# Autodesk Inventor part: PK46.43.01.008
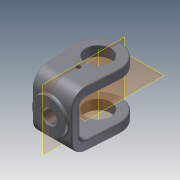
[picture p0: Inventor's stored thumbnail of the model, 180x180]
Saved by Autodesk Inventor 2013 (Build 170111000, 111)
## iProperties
Shininess: 64.0
Length Units: 11269
Angle Units: 11279
Time Units: 11290
Mass Units: 11283
Length Display Precision: 3
Angle Display Precision: 2
Compacted: True
Part Number: PK46.43.01.008
Document SubType Name: Modeling
Created: 2004-11
Material: Steel, High Strength Low Alloy
Designer: ELarisa
Manufacturer: Standard
Standards Organization: Custom
Density: 7.84 g/cm^3
Density: 0.0
Volumn: 0.0
Area: 0.0
PropertySet Name: Model Information
Control State: 0
Master: False
Checked Out: False
Checked Out Date: 2008-10-09
Last Check In Date: 2008-10-09
Author: ELarisa
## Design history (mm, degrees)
sketch "Эскиз1"
  geometry: L1 (118.504, -3.432)-(118.504, -3.593); L2 (188.504, -10.209)-(48.504, -10.209); L3 (48.504, -10.209)-(38.655, 149.878); L4 (188.504, -10.209)-(198.353, 149.878); A1 r 80 centre (118.504, 154.791) between (198.353, 149.878) and (38.655, 149.878)
  constraints: 8 end point, 2 point on circle, 2 symmetric about line, 1 centre point, 1 perpendicular, 1 tangent, 1 other
  dimensions: "d0" = 80 radius of A1; "d1" = 140 distance of L2.start L2.end; "d2" = 165 distance from line of L2 A1.centre
extrude "Выдавливание1" new body sketch "Эскиз1" distance "d3" = 200; taper "d4" = 0 deg
workaxis "Work Axis1"
fillet "Сопряжение1" dims "d5" = 50
workplane "Work Plane3"
sketch "Эскиз2"
  geometry: L1 (35, 130)-(165, 130); L2 (165, 130)-(165, -150); L3 (165, -150)-(35, -150); L4 (35, -150)-(35, 130); L5 (0, -19.512)-(0, 70); L6 (-40, 0)-(240, 0) reference; L7 (50, 165)-(150, 165) reference; L8 (200, 4.913)-(200, 115) reference; L9 (0, 115)-(0, 4.913) reference
  constraints: 10 end point, 2 parallel, 1 collinear, 1 horizontal, 1 perpendicular
  dimensions: "d7" = 35 distance between parallel lines of L4 L5; "d42" = 35 distance between parallel lines of L7 L1; "d43" = 280 distance of L3.end L1.start; "d66" = 35 distance between parallel lines of L8 L2 (= d7)
extrude "Выдавливание2" cut sketch "Эскиз2" stored distance "d10" = 200; taper "d11" = 0 deg
node "РабПлоскость1"
sketch "Эскиз5"
  geometry: L1 (0, 0)-(0, 100) reference; L2 (143.076, 150)-(-3.076, 150) reference; C1 r 60 at (70, 50)
  constraints: 1 centre point
  dimensions: "d24" = 120 diameter of C1; "d25" = 100 distance from line of L2 C1.centre; "d26" = 70 distance from line of L1 C1.centre
extrude "Выдавливание4" join sketch "Эскиз5" distance "d27" = 10; taper "d28" = 0 deg
sketch "Sketch7"
  geometry: C1 r 60 at (0, 0) reference
hole "Hole3" sketch "Sketch7" at (0, 0) diameter "d46" = 49.835; stored, may be unused: countersink angle "d50" = 82 deg, drill point angle "d52" = 118 deg; dims "d47" = 6, "d48" = 56, "d49" = 2, "d51" = 8
fillet "Fillet4" dims "d53" = 20
sketch "Sketch8"
  geometry: A1 r 80 centre (-118.504, 154.791) between (-38.655, 149.878) and (-198.353, 149.878) reference
hole "Hole4" sketch "Sketch8" at (-118.504, 154.791) diameter "d54" = 90; stored, may be unused: countersink angle "d58" = 82 deg, drill point angle "d60" = 118 deg; dims "d55" = 6, "d56" = 68, "d57" = 2, "d59" = 8
sketch "Эскиз9"
  geometry: L1 (118.504, 283.791)-(118.504, -59.209) reference; C1 r 8 at (118.504, 84.791); 1 further point
  constraints: 1 centre point
  dimensions: "d61" = 0 distance from line of L1 C1.centre; "d62" = 70 distance of point (118.504, 154.791) C1.centre; "d63" = 16 diameter of C1
extrude "Выдавливание5" cut sketch "Эскиз9" stored distance "d64" = 10; taper "d65" = 0 deg
fillet "Сопряжение6" dims "d73" = 15, "d74" = 15, "d75" = 5, "d76" = 0, "d77" = 15, "d78" = 0, "d79" = 15, "d80" = 0, "d81" = 5, "d82" = 0, "d83" = 5, "d84" = 0, "d85" = 5, "d86" = 0, "d87" = 15, "d88" = 0, "d89" = 15, "d90" = 0, "d91" = 5, "d92" = 0, "d96" = 5, "d97" = 10
fillet "Сопряжение7" dims "d93" = 5
fillet "Сопряжение8" dims "d94" = 5
fillet "Сопряжение9" dims "d95" = 5
body "Solid1"
other parameters: "d41" = 90 deg
